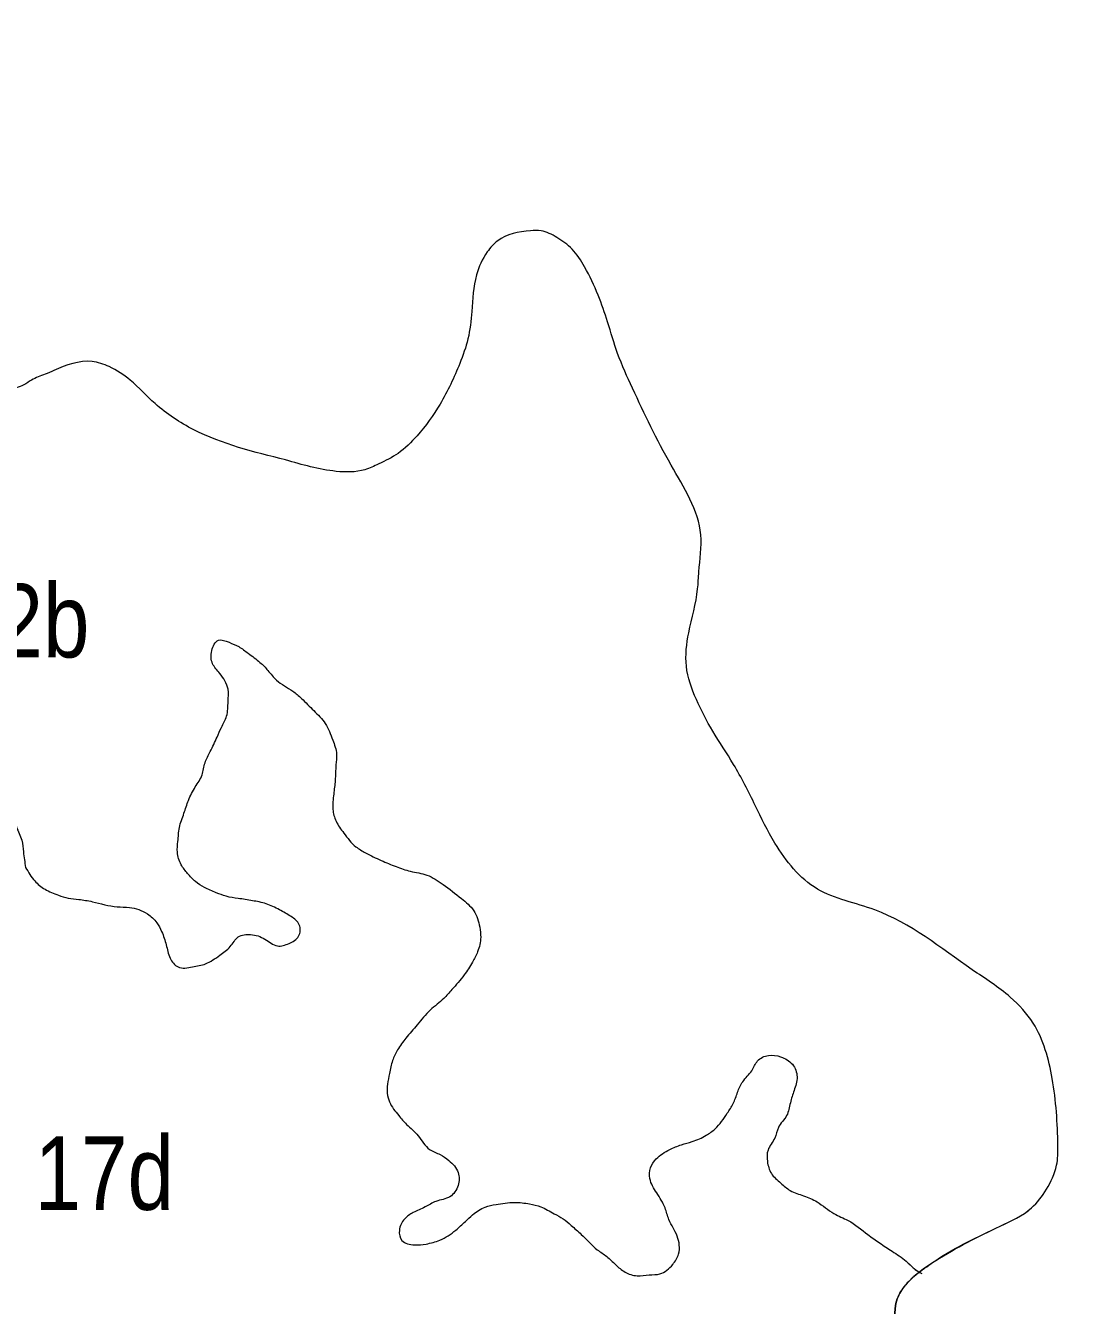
# Model space of a CAD drawing. Extents: x 854879 to 917879, y 8541948 to 8631048.
# Drawn here: x 891328 to 896773, y 8605093 to 8611712 of the extents above; entities that cross this region are included whole.
import ezdxf
from ezdxf.enums import TextEntityAlignment as Align

# ---------------------------------------------------------------- set-up
doc = ezdxf.new("R2010")
doc.units = 0
doc.header["$LTSCALE"] = 150
for name, color, linetype, lineweight in [('1', 7, 'Continuous', 13), ('12', 7, 'Continuous', 13), ('35', 7, 'Continuous', 13), ('50', 7, 'Continuous', 13)]:
    doc.layers.add(name, color=color, linetype=linetype, lineweight=lineweight)

msp = doc.modelspace()

# ---------------------------------------------------------------- linework, layer by layer
at = {"layer": '12'}
for points in [[(892672.9, 8609465.7), (892198, 8609621.7), (891998.2, 8609756.6), (891869.6, 8609877.9), (891760.9, 8609948), (891672, 8609974.5), (891475.1, 8609928.5), (891429, 8609908.6), (891359.8, 8609878.9), (891318.7, 8609853.9), (891241.9, 8609826.8), (891167.7, 8609799.7), (891085.8, 8609777.7), (890871.6, 8609770.1), (890792.6, 8609771), (890700.8, 8609772.1), (890588.7, 8609778.5), (890319.2, 8609835.3), (890207.7, 8609892.7), (889977.6, 8610050.9), (889903.9, 8610074.7), (889832.8, 8610093.4), (889748.7, 8610102), (889669.4, 8610077.5), (889612.4, 8610001.7), (889606.1, 8609899.9), (889615, 8609790.2), (889613.5, 8609665.3), (889566.5, 8609566.5), (889468.9, 8609509.1), (889374.5, 8609500), (889229, 8609483.9), (889139.1, 8609426.4), (889019.3, 8609216.3), (889000.1, 8609104.4), (888948.1, 8609010.8), (888873.1, 8608925), (888721.8, 8608852.9), (888580.9, 8608793.4), (888460.8, 8608764.3), (888340.7, 8608747.9), (888259.3, 8608756.5), (888157.7, 8608793.4), (887962.4, 8608877.3), (887885.8, 8608860.4), (887801, 8608810.4), (887731.8, 8608778.1), (887632, 8608746.2), (887466.7, 8608776.2), (887378.2, 8608841), (887340.3, 8608872), (887274.9, 8608941.6), (887197.2, 8609054.6), (887162.8, 8609167.2), (887122, 8609379.2), (887160, 8609783.9), (887115, 8609863.4), (887044.5, 8609935.6), (886960.9, 8609982.5), (886775.5, 8610040.8), (886503.5, 8610102.6), (886312.8, 8610148.2), (886016.4, 8610302.1), (885909.8, 8610339.1), (885825.9, 8610357.9), (885767.2, 8610358.6), (885634.6, 8610355.1), (885423, 8610347.5), (885336.5, 8610361.2), (885260.2, 8610385.1), (885201.9, 8610411.3), (885163.8, 8610421.9), (884758.9, 8610671.4), (884634.5, 8610716.2), (884510.2, 8610771.2), (884457.5, 8610833), (884387.7, 8610968.9), (884375.6, 8611025.1), (884356, 8611094.1), (884318.6, 8611160.8), (884238.1, 8611251), (884169.8, 8611295.1), (884004.9, 8611368.5), (883944.2, 8611407.4), (883908.9, 8611435.9), (883845.9, 8611502.9), (883805.9, 8611564.5), (883707.7, 8611670.2), (883636.7, 8611699), (883542.5, 8611710.4), (883458.2, 8611696.1)], [(898709.6, 8597663.7), (898579.1, 8597838.5), (898432.9, 8597977.9), (898371.8, 8597988.8), (898303.2, 8598002.4), (898232.5, 8598059.3), (898192.5, 8598131.1), (898160.3, 8598210.5), (898140.9, 8598294.8), (898094, 8598422.8), (897974.2, 8598635.7), (897782.9, 8598847), (897694.9, 8598944.9), (897581.8, 8599078.7), (897454.1, 8599276.5), (897414.3, 8599358.5), (897347.7, 8599759.4), (897308.1, 8599859.2), (897226.2, 8600048.8), (897167.2, 8600230.4), (897069.7, 8600613.8), (897060.2, 8601100.7), (897034.4, 8601289.5), (896995.3, 8601646.8), (896974.8, 8602067.5), (896984.2, 8602207.5), (896998.9, 8602378.1), (896999.8, 8602663.5), (897010.2, 8602892.7), (897015.1, 8603091.4), (896942.2, 8603395.5), (896869.4, 8603490.7), (896784.2, 8603616.6), (896637.5, 8603715.2), (896459.5, 8603750.4), (896334.5, 8603741.7), (896227.5, 8603745.5), (896026.7, 8604018.1), (895961.7, 8604118.2), (895901.9, 8604241.3), (895852.2, 8604343.8), (895836.1, 8604494.3), (895838.6, 8604700.7), (895836.1, 8604919.9), (895836, 8605126.3), (895880.2, 8605199.7), (896034.6, 8605325.2), (896368.1, 8605502.2), (896529.9, 8605597.1), (896607.5, 8605693), (896660, 8605817.2), (896666.3, 8605919.1), (896637.2, 8606266), (896538.7, 8606552.6), (896420.5, 8606686.5), (896223.3, 8606829), (895719.7, 8607138.3), (895422.7, 8607246.3), (895203.7, 8607483.4), (895101.5, 8607678.3), (894989.3, 8607891.1), (894881.7, 8608063.1), (894797, 8608227.2), (894745.5, 8608398.6), (894757.8, 8608571.7), (894803.8, 8608798), (894810, 8608887.1), (894819.9, 8609078.1), (894666.1, 8609439.2), (894466.9, 8609836.6), (894390, 8610015.9), (894338.4, 8610179.6), (894289.1, 8610317.8), (894219.4, 8610463.9), (894154.2, 8610556.4), (894075.9, 8610616), (893994.7, 8610650.1), (893938.7, 8610650.7), (893769.8, 8610599.2), (893715.6, 8610541.3), (893660.6, 8610422.2), (893635.4, 8610233.9), (893615.9, 8610091.4), (893573.6, 8609964.5), (893471.7, 8609754.2), (893352.5, 8609590), (893254.5, 8609499.5), (893154.4, 8609444.6), (893082.7, 8609414.9), (892934.8, 8609406.4), (892672.9, 8609465.7)]]:
    msp.add_spline(points, degree=3, dxfattribs=at)
at = {"layer": '35'}
for points in [[(891328.5, 8607358), (891376, 8607287.8), (891428.9, 8607245.2), (891498.1, 8607213.8), (891548.6, 8607199.2), (891603.4, 8607192.4), (891673.7, 8607180.8), (891802.3, 8607154.2), (891865.2, 8607150.9), (891958.1, 8607118.2), (892006.8, 8607071.8), (892032, 8607026.7), (892055.8, 8606957.8), (892075.8, 8606889), (892116.7, 8606843.1), (892191.6, 8606843.2), (892259.5, 8606859.6), (892332.8, 8606903.6), (892386.4, 8606948.6), (892428.5, 8606998.2), (892492.2, 8607010.8), (892565.9, 8606987.1), (892631, 8606951.8), (892690.8, 8606964.6), (892740.1, 8607001.9), (892743.3, 8607061.5), (892702.2, 8607103.4), (892641, 8607138.5), (892571.8, 8607170), (892501.7, 8607185.6), (892427.4, 8607197.4), (892365, 8607208.6), (892314.7, 8607227.1), (892253.1, 8607254.2), (892207.4, 8607284.5), (892166.3, 8607326.4), (892133.3, 8607372), (892113.2, 8607436.8), (892116.2, 8607492.4), (892123.9, 8607563.7), (892147.6, 8607638.1), (892170.9, 8607704.6), (892206.2, 8607774.5), (892241.1, 8607836.4), (892256.3, 8607899.3), (892283.1, 8607957.7), (892318.6, 8608031.5), (892341, 8608082.1), (892367.8, 8608140.5), (892375.8, 8608215.8), (892375.3, 8608279.5), (892332.4, 8608361.4), (892295.7, 8608411.1), (892291.4, 8608479.1), (892325.9, 8608533), (892380.5, 8608522.2), (892430.5, 8608499.7), (892479.9, 8608465.3), (892540.4, 8608418.3), (892581.5, 8608376.4), (892626.1, 8608326.2), (892709.8, 8608270.1), (892755.1, 8608231.9), (892818.7, 8608168.9), (892878.1, 8608102.1), (892916.9, 8608016.4), (892936.6, 8607943.7), (892933.6, 8607888.1), (892929.3, 8607808.6), (892921.6, 8607737.3), (892917.3, 8607657.9), (892933.7, 8607597.3), (892973.8, 8607535.5), (893036.9, 8607464.5), (893086.5, 8607434), (893167.2, 8607394), (893244.3, 8607362.1), (893317.9, 8607338.3), (893403.5, 8607318), (893487.6, 8607269.8), (893582.2, 8607197.2), (893645.8, 8607134.1), (893676.7, 8607048.9), (893681.8, 8606996.8), (893666, 8606922), (893639.4, 8606867.6), (893596.4, 8606802.1), (893533.2, 8606725.7), (893491.3, 8606680.1), (893421.1, 8606620), (893353.9, 8606543.8)], [(889158.7, 8606295.6), (889146.8, 8606220.6), (889198.2, 8606150.2), (889258.7, 8606103.2), (889311, 8606048.7), (889358.2, 8605974.6), (889382.1, 8605905.6), (889373.9, 8605826.4), (889369.8, 8605750.9), (889335.8, 8605704.9), (889313.6, 8605658.2), (889264.3, 8605621), (889218.9, 8605583.5), (889158.1, 8605550.8), (889089.7, 8605526.5), (888977.6, 8605492.5), (888961.9, 8605421.6), (888999.1, 8605379.8), (889057.2, 8605360.9), (889116.1, 8605357.8), (889186.2, 8605342.2), (889234.6, 8605287.9), (889275.4, 8605242), (889329, 8605211.3), (889411.3, 8605203.1), (889486.4, 8605207.2), (889566.1, 8605222.9), (889627.6, 8605267.5), (889710.5, 8605342.9), (889733.3, 8605401.4), (889737, 8605469), (889741, 8605544.4), (889724.8, 8605609), (889717.1, 8605685.1), (889732.3, 8605748), (889759.3, 8605810.4), (889793.5, 8605860.4), (889838.9, 8605897.8), (889912, 8605937.9), (889978.8, 8605934.4), (890028.4, 8605903.9), (890078, 8605873.5), (890132.8, 8605866.7), (890213.3, 8605898.3), (890263.5, 8605951.5), (890285.9, 8606002.1), (890304.4, 8606052.9), (890316.6, 8606131.9), (890319.8, 8606191.5), (890362.5, 8606253.1), (890397, 8606307), (890434.2, 8606340.9), (890487.5, 8606378), (890540.5, 8606411.1), (890589.4, 8606440.4), (890645.7, 8606461.4), (890710.9, 8606501.8), (890780.5, 8606550), (890814.5, 8606596), (890793.5, 8606644.9), (890728.4, 8606680.2), (890667.2, 8606715.2), (890662.8, 8606779.2), (890673.6, 8606834.4), (890680.3, 8606885.8), (890683.8, 8606949.3), (890691.6, 8607020.6), (890681, 8607116.8), (890626.7, 8607207.2), (890597.4, 8607248.6), (890568.3, 8607293.9), (890528.3, 8607355.7), (890543.3, 8607414.7), (890558.1, 8607469.7), (890592.5, 8607523.7), (890632.2, 8607601.3), (890662.5, 8607651.5), (890725.7, 8607727.9), (890786.8, 8607764.5), (890859.5, 8607796.6), (890951.1, 8607815.8), (891018.4, 8607820.2), (891092.4, 8607804.4), (891149.7, 8607769.6), (891194.7, 8607727.4), (891250.7, 8607668.8), (891267.7, 8607620.1), (891280.7, 8607567.6), (891308.5, 8607498.4), (891317.1, 8607438.3), (891328.5, 8607358)], [(893353.9, 8606543.8), (893295.1, 8606475.2), (893252.3, 8606413.7), (893225.8, 8606359.3), (893210.3, 8606292.4), (893199.5, 8606237.2), (893210.3, 8606145), (893257.7, 8606074.8), (893298.6, 8606028.9), (893358.5, 8605970), (893417.8, 8605899.2), (893471.5, 8605872.5), (893517.2, 8605842.3), (893565.1, 8605780), (893565.4, 8605712.3), (893522.8, 8605654.8), (893450.6, 8605630.6), (893393.9, 8605601.7), (893333.2, 8605573), (893288.1, 8605539.5), (893261.3, 8605481.2), (893274.2, 8605428.7), (893340, 8605405.4), (893399.3, 8605410.2), (893471.4, 8605430.4), (893553, 8605481.9), (893602.7, 8605527.2), (893640, 8605561.1), (893705.2, 8605601.5), (893761.1, 8605614.5), (893856.3, 8605625.5), (893934.7, 8605617.5), (893993, 8605602.5), (894062.1, 8605567), (894107.9, 8605540.8), (894149.5, 8605506.7), (894202.1, 8605460.2), (894284.5, 8605380.2), (894333.9, 8605345.8), (894379, 8605303.6), (894428.1, 8605265.2), (894490.2, 8605246.1), (894553.5, 8605250.7), (894608.9, 8605255.8), (894674.6, 8605304.2), (894705.1, 8605358.4), (894698.2, 8605450.3), (894655.5, 8605536.2), (894635.2, 8605597), (894592.1, 8605674.9), (894556.6, 8605748.5), (894559.6, 8605804.1), (894589.7, 8605850.3), (894659.3, 8605898.5), (894719.7, 8605923.2), (894775.8, 8605940.2), (894848.5, 8605972.3), (894893.7, 8606005.8), (894927.2, 8606043.9), (894957.1, 8606086.2), (894987.4, 8606136.4), (895010.2, 8606194.9), (895036.8, 8606249.3), (895083.3, 8606306.7), (895113.6, 8606356.9), (895170.3, 8606385.8), (895233, 8606378.5), (895293.9, 8606339.5), (895318, 8606274.6), (895302.4, 8606203.7), (895283.2, 8606140.9), (895263.9, 8606074.2), (895221.2, 8606012.7), (895202.5, 8605957.9), (895167.6, 8605896), (895164.4, 8605836.4), (895184.8, 8605775.6), (895233.3, 8605725.3), (895282.5, 8605686.9), (895351.9, 8605659.4), (895421.2, 8605627.9), (895508.6, 8605567.6), (895581.5, 8605531.9), (895684, 8605458.9), (895744.8, 8605415.9), (895809.5, 8605372.7), (895881.6, 8605321.2), (895922.9, 8605283.2), (895949.4, 8605265.2)], [(895948.3, 8605264.3), (895880.2, 8605199.7), (895836, 8605126.3), (895836.1, 8604919.9), (895838.6, 8604700.7), (895836.1, 8604494.3), (895852.2, 8604343.8), (895901.9, 8604241.3), (895961.7, 8604118.2), (896026.7, 8604018.1), (896227.5, 8603745.5), (896334.5, 8603741.7), (896459.5, 8603750.4), (896637.5, 8603715.2), (896784.2, 8603616.6), (896869.4, 8603490.7), (896942.2, 8603395.5), (897015.1, 8603095.7)]]:
    msp.add_spline(points, degree=3, dxfattribs=at)
at = {"layer": '50'}
for points in [[(895942.6, 8605259.3), (896034.6, 8605325.2), (896368.1, 8605502.2), (896529.9, 8605597.1), (896607.5, 8605693), (896660, 8605817.2), (896666.3, 8605919.1), (896637.2, 8606266), (896538.7, 8606552.6), (896420.5, 8606686.5), (896223.3, 8606829), (895719.7, 8607138.3), (895422.7, 8607246.3), (895203.7, 8607483.4), (895101.5, 8607678.3), (894989.3, 8607891.1), (894881.7, 8608063.1), (894797, 8608227.2), (894745.5, 8608398.6), (894757.8, 8608571.7), (894803.8, 8608798), (894810, 8608887.1), (894819.9, 8609078.1), (894666.1, 8609439.2), (894466.9, 8609836.6), (894390, 8610015.9), (894338.4, 8610179.6), (894289.1, 8610317.8), (894219.4, 8610463.9), (894154.2, 8610556.4), (894075.9, 8610616), (893994.7, 8610650.1), (893938.7, 8610650.7), (893769.8, 8610599.2), (893715.6, 8610541.3), (893660.6, 8610422.2), (893635.4, 8610233.9), (893615.9, 8610091.4), (893573.6, 8609964.5), (893471.7, 8609754.2), (893352.5, 8609590), (893254.5, 8609499.5), (893154.4, 8609444.6), (893082.7, 8609414.9), (892934.8, 8609406.4), (892672.9, 8609465.7)], [(892672.9, 8609465.7), (892198, 8609621.7), (891998.2, 8609756.6), (891869.6, 8609877.9), (891760.9, 8609948), (891672, 8609974.5), (891475.1, 8609928.5), (891429, 8609908.6), (891359.8, 8609878.9), (891318.7, 8609853.9), (891241.9, 8609826.8), (891167.7, 8609799.7), (891085.8, 8609777.7), (890871.6, 8609770.1), (890792.6, 8609771), (890700.8, 8609772.1), (890588.7, 8609778.5), (890319.2, 8609835.3), (890207.7, 8609892.7), (889977.6, 8610050.9), (889903.9, 8610074.7), (889832.8, 8610093.4), (889832.2, 8610093.5)], [(891328.5, 8607358), (891376, 8607287.8), (891428.9, 8607245.2), (891498.1, 8607213.8), (891548.6, 8607199.2), (891603.4, 8607192.4), (891673.7, 8607180.8), (891802.3, 8607154.2), (891865.2, 8607150.9), (891958.1, 8607118.2), (892006.8, 8607071.8), (892032, 8607026.7), (892055.8, 8606957.8), (892075.8, 8606889), (892116.7, 8606843.1), (892191.6, 8606843.2), (892259.5, 8606859.6), (892332.8, 8606903.6), (892386.4, 8606948.6), (892428.5, 8606998.2), (892492.2, 8607010.8), (892565.9, 8606987.1), (892631, 8606951.8), (892690.8, 8606964.6), (892740.1, 8607001.9), (892743.3, 8607061.5), (892702.2, 8607103.4), (892641, 8607138.5), (892571.8, 8607170), (892501.7, 8607185.6), (892427.4, 8607197.4), (892365, 8607208.6), (892314.7, 8607227.1), (892253.1, 8607254.2), (892207.4, 8607284.5), (892166.3, 8607326.4), (892133.3, 8607372), (892113.2, 8607436.8), (892116.2, 8607492.4), (892123.9, 8607563.7), (892147.6, 8607638.1), (892170.9, 8607704.6), (892206.2, 8607774.5), (892241.1, 8607836.4), (892256.3, 8607899.3), (892283.1, 8607957.7), (892318.6, 8608031.5), (892341, 8608082.1), (892367.8, 8608140.5), (892375.8, 8608215.8), (892375.3, 8608279.5), (892332.4, 8608361.4), (892295.7, 8608411.1), (892291.4, 8608479.1), (892325.9, 8608533), (892380.5, 8608522.2), (892430.5, 8608499.7), (892479.9, 8608465.3), (892540.4, 8608418.3), (892581.5, 8608376.4), (892626.1, 8608326.2), (892709.8, 8608270.1), (892755.1, 8608231.9), (892818.7, 8608168.9), (892878.1, 8608102.1), (892916.9, 8608016.4), (892936.6, 8607943.7), (892933.6, 8607888.1), (892929.3, 8607808.6), (892921.6, 8607737.3), (892917.3, 8607657.9), (892933.7, 8607597.3), (892973.8, 8607535.5), (893036.9, 8607464.5), (893086.5, 8607434), (893167.2, 8607394), (893244.3, 8607362.1), (893317.9, 8607338.3), (893403.5, 8607318), (893487.6, 8607269.8), (893582.2, 8607197.2), (893645.8, 8607134.1), (893676.7, 8607048.9), (893681.8, 8606996.8), (893666, 8606922), (893639.4, 8606867.6), (893596.4, 8606802.1), (893533.2, 8606725.7), (893491.3, 8606680.1), (893421.1, 8606620), (893353.9, 8606543.8)], [(889158.7, 8606295.6), (889146.8, 8606220.6), (889198.2, 8606150.2), (889258.7, 8606103.2), (889311, 8606048.7), (889358.2, 8605974.6), (889382.1, 8605905.6), (889373.9, 8605826.4), (889369.8, 8605750.9), (889335.8, 8605704.9), (889313.6, 8605658.2), (889264.3, 8605621), (889218.9, 8605583.5), (889158.1, 8605550.8), (889089.7, 8605526.5), (888977.6, 8605492.5), (888961.9, 8605421.6), (888999.1, 8605379.8), (889057.2, 8605360.9), (889116.1, 8605357.8), (889186.2, 8605342.2), (889234.6, 8605287.9), (889275.4, 8605242), (889329, 8605211.3), (889411.3, 8605203.1), (889486.4, 8605207.2), (889566.1, 8605222.9), (889627.6, 8605267.5), (889710.5, 8605342.9), (889733.3, 8605401.4), (889737, 8605469), (889741, 8605544.4), (889724.8, 8605609), (889717.1, 8605685.1), (889732.3, 8605748), (889759.3, 8605810.4), (889793.5, 8605860.4), (889838.9, 8605897.8), (889912, 8605937.9), (889978.8, 8605934.4), (890028.4, 8605903.9), (890078, 8605873.5), (890132.8, 8605866.7), (890213.3, 8605898.3), (890263.5, 8605951.5), (890285.9, 8606002.1), (890304.4, 8606052.9), (890316.6, 8606131.9), (890319.8, 8606191.5), (890362.5, 8606253.1), (890397, 8606307), (890434.2, 8606340.9), (890487.5, 8606378), (890540.5, 8606411.1), (890589.4, 8606440.4), (890645.7, 8606461.4), (890710.9, 8606501.8), (890780.5, 8606550), (890814.5, 8606596), (890793.5, 8606644.9), (890728.4, 8606680.2), (890667.2, 8606715.2), (890662.8, 8606779.2), (890673.6, 8606834.4), (890680.3, 8606885.8), (890683.8, 8606949.3), (890691.6, 8607020.6), (890681, 8607116.8), (890626.7, 8607207.2), (890597.4, 8607248.6), (890568.3, 8607293.9), (890528.3, 8607355.7), (890543.3, 8607414.7), (890558.1, 8607469.7), (890592.5, 8607523.7), (890632.2, 8607601.3), (890662.5, 8607651.5), (890725.7, 8607727.9), (890786.8, 8607764.5), (890859.5, 8607796.6), (890951.1, 8607815.8), (891018.4, 8607820.2), (891092.4, 8607804.4), (891149.7, 8607769.6), (891194.7, 8607727.4), (891250.7, 8607668.8), (891267.7, 8607620.1), (891280.7, 8607567.6), (891308.5, 8607498.4), (891317.1, 8607438.3), (891328.5, 8607358)], [(893353.9, 8606543.8), (893295.1, 8606475.2), (893252.3, 8606413.7), (893225.8, 8606359.3), (893210.3, 8606292.4), (893199.5, 8606237.2), (893210.3, 8606145), (893257.7, 8606074.8), (893298.6, 8606028.9), (893358.5, 8605970), (893417.8, 8605899.2), (893471.5, 8605872.5), (893517.2, 8605842.3), (893565.1, 8605780), (893565.4, 8605712.3), (893522.8, 8605654.8), (893450.6, 8605630.6), (893393.9, 8605601.7), (893333.2, 8605573), (893288.1, 8605539.5), (893261.3, 8605481.2), (893274.2, 8605428.7), (893340, 8605405.4), (893399.3, 8605410.2), (893471.4, 8605430.4), (893553, 8605481.9), (893602.7, 8605527.2), (893640, 8605561.1), (893705.2, 8605601.5), (893761.1, 8605614.5), (893856.3, 8605625.5), (893934.7, 8605617.5), (893993, 8605602.5), (894062.1, 8605567), (894107.9, 8605540.8), (894149.5, 8605506.7), (894202.1, 8605460.2), (894284.5, 8605380.2), (894333.9, 8605345.8), (894379, 8605303.6), (894428.1, 8605265.2), (894490.2, 8605246.1), (894553.5, 8605250.7), (894608.9, 8605255.8), (894674.6, 8605304.2), (894705.1, 8605358.4), (894698.2, 8605450.3), (894655.5, 8605536.2), (894635.2, 8605597), (894592.1, 8605674.9), (894556.6, 8605748.5), (894559.6, 8605804.1), (894589.7, 8605850.3), (894659.3, 8605898.5), (894719.7, 8605923.2), (894775.8, 8605940.2), (894848.5, 8605972.3), (894893.7, 8606005.8), (894927.2, 8606043.9), (894957.1, 8606086.2), (894987.4, 8606136.4), (895010.2, 8606194.9), (895036.8, 8606249.3), (895083.3, 8606306.7), (895113.6, 8606356.9), (895170.3, 8606385.8), (895233, 8606378.5), (895293.9, 8606339.5), (895318, 8606274.6), (895302.4, 8606203.7), (895283.2, 8606140.9), (895263.9, 8606074.2), (895221.2, 8606012.7), (895202.5, 8605957.9), (895167.6, 8605896), (895164.4, 8605836.4), (895184.8, 8605775.6), (895233.3, 8605725.3), (895282.5, 8605686.9), (895351.9, 8605659.4), (895421.2, 8605627.9), (895508.6, 8605567.6), (895581.5, 8605531.9), (895684, 8605458.9), (895744.8, 8605415.9), (895809.5, 8605372.7), (895881.6, 8605321.2), (895922.9, 8605283.2), (895962.6, 8605257.1)]]:
    msp.add_spline(points, degree=3, dxfattribs=at)

# ---------------------------------------------------------------- texts
at = {"layer": '1', "width": 0.85}
for s, p in [('12b', (891298.4, 8608444)), ('17d', (891735.4, 8605586.8))]:
    msp.add_text(s, height=380, dxfattribs=at).set_placement(p, align=Align.CENTER)

doc.saveas('drawing.dxf')
